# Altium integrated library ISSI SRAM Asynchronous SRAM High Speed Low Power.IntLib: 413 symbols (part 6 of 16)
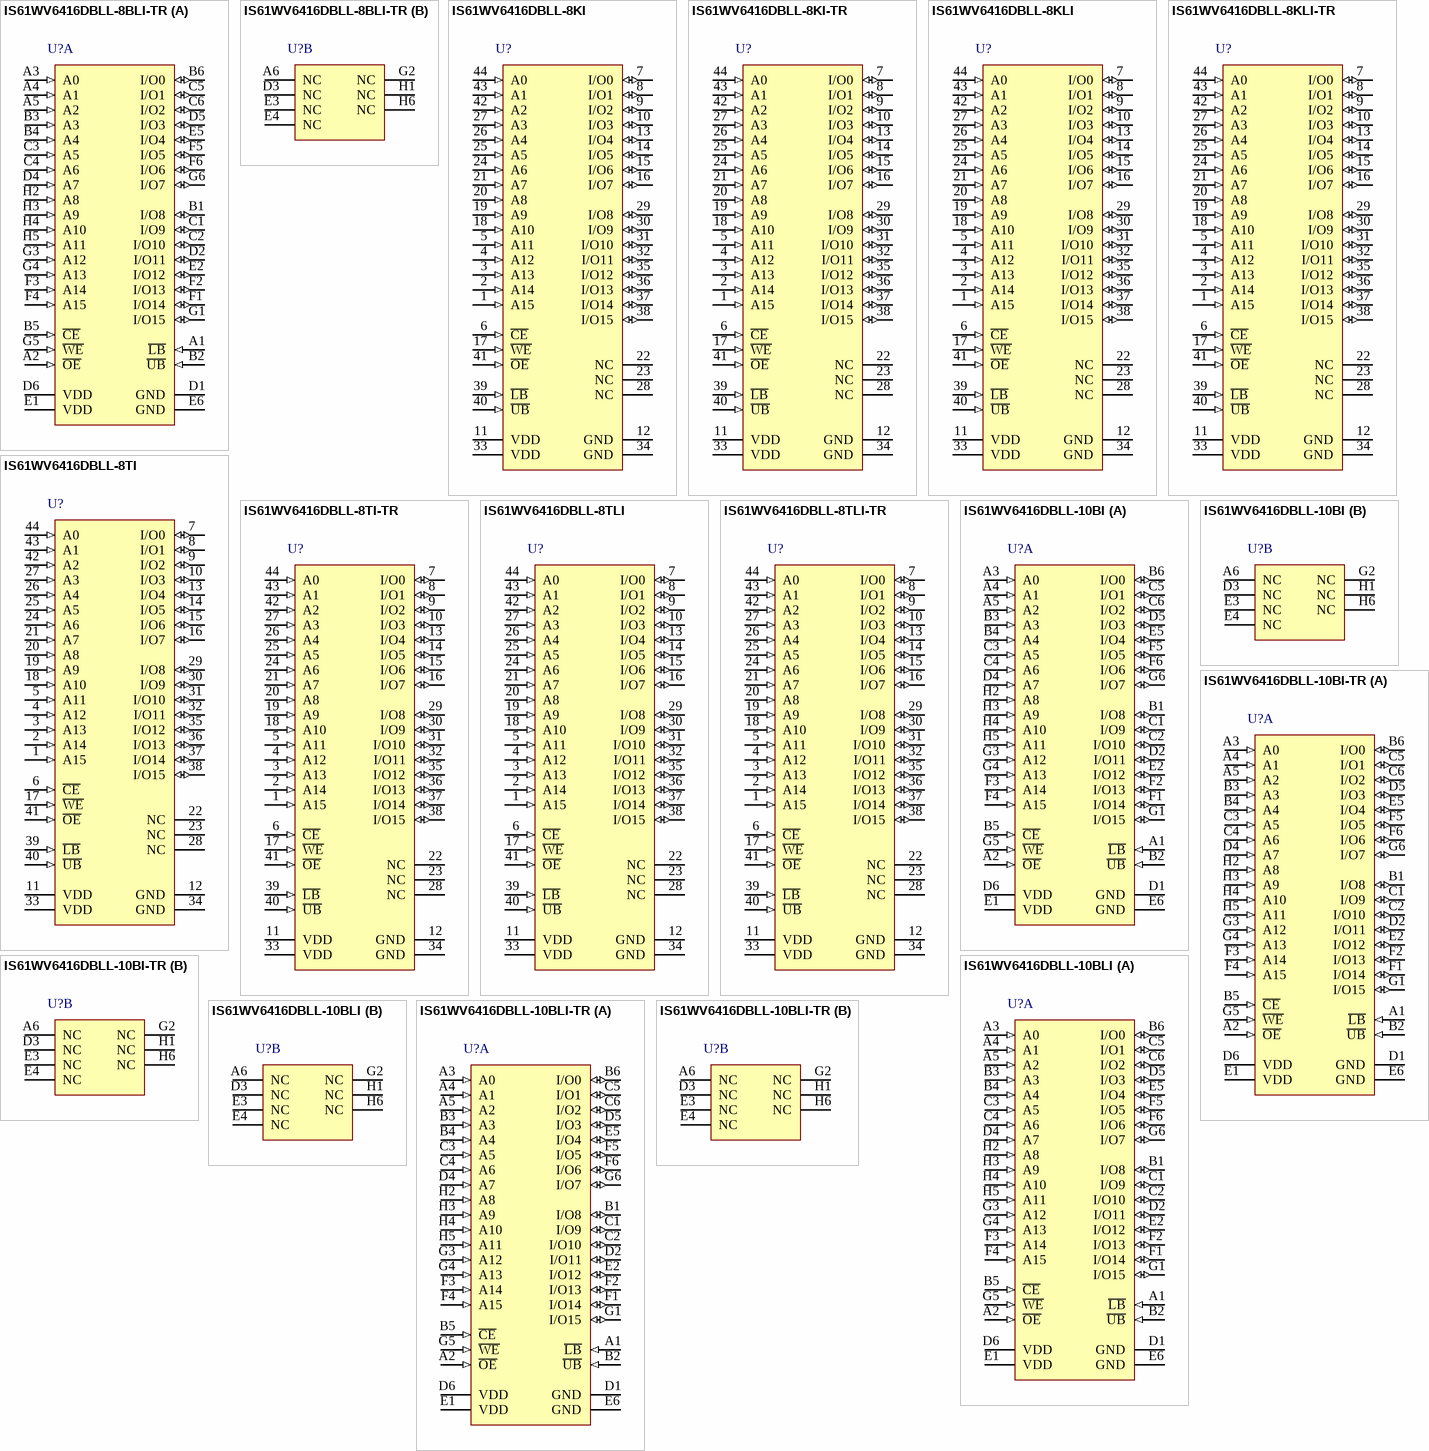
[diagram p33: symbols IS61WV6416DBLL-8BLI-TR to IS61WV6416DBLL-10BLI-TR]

## IS61WV6416DBLL-8BLI-TR
designator U?
1 M High Speed Asynchronous CMOS SRAM, 64 K x 16, -40 to 85 degC, 48-Pin BGA (TF-BGA-48), Pb-Free; Manufacturer: Integrated Silicon Solution Inc (ISSI); PartNumber: IS61WV6416DBLL-8BLI-TR; Density: 1M; Organization: 64K x 16; Packing: Tape & Reel; Speed (ns): 8
footprint ISSI-TF-BGA-48-6000X8000DE (BGA, 48-Balls, Body 8x6mm, Pitch 0.75mm)
part A pins: A1 ~{LB} (in) "Lower-byte Control (I/O0-I/O7)", A2 ~{OE} (in) "Output Enable Input", A3 A0 (in) "Address Input", A4 A1 (in) "Address Input", A5 A2 (in) "Address Input", B1 I/O8 (io) "Data Input/Output", B2 ~{UB} (in) "Upper-byte Control (I/O8-I/O15)", B3 A3 (in) "Address Input", B4 A4 (in) "Address Input", B5 ~{CE} (in) "Chip Enable Input", B6 I/O0 (io) "Data Input/Output", C1 I/O9 (io) "Data Input/Output", C2 I/O10 (io) "Data Input/Output", C3 A5 (in) "Address Input", C4 A6 (in) "Address Input", C5 I/O1 (io) "Data Input/Output", C6 I/O2 (io) "Data Input/Output", D1 GND (power) "Ground", D2 I/O11 (io) "Data Input/Output", D4 A7 (in) "Address Input", D5 I/O3 (io) "Data Input/Output", D6 VDD (power) "Power", E1 VDD (power) "Power", E2 I/O12 (io) "Data Input/Output", E5 I/O4 (io) "Data Input/Output", E6 GND (power) "Ground", F1 I/O14 (io) "Data Input/Output", F2 I/O13 (io) "Data Input/Output", F3 A14 (in) "Address Input", F4 A15 (in) "Address Input", F5 I/O5 (io) "Data Input/Output", F6 I/O6 (io) "Data Input/Output", G1 I/O15 (io) "Data Input/Output", G3 A12 (in) "Address Input", G4 A13 (in) "Address Input", G5 ~{WE} (in) "Write Enable Input", G6 I/O7 (io) "Data Input/Output", H2 A8 (in) "Address Input", H3 A9 (in) "Address Input", H4 A10 (in) "Address Input", H5 A11 (in) "Address Input"
part B pins: A6 NC "No Connection", D3 NC "No Connection", E3 NC "No Connection", E4 NC "No Connection", G2 NC "No Connection", H1 NC "No Connection", H6 NC "No Connection"

## IS61WV6416DBLL-8KI
designator U?
1 M High Speed Asynchronous CMOS SRAM, 64 K x 16, -40 to 85 degC, 44-Pin SOJ (SOJ-44); Manufacturer: Integrated Silicon Solution Inc (ISSI); PartNumber: IS61WV6416DBLL-8KI; Density: 1M; Organization: 64K x 16; Packing: Tray / Tube; Speed (ns): 8
footprint ISSI-SOJ-44_N (SOJ, 44-Leads, Body 28.7x10.29mm, Pitch 1.27mm, IPC Medium Density)
pins: 1 A15 (in) "Address Inputs", 2 A14 (in) "Address Inputs", 3 A13 (in) "Address Inputs", 4 A12 (in) "Address Inputs", 5 A11 (in) "Address Inputs", 6 ~{CE} (in) "Chip Enable Input", 7 I/O0 (io) "Data Inputs/Outputs", 8 I/O1 (io) "Data Inputs/Outputs", 9 I/O2 (io) "Data Inputs/Outputs", 10 I/O3 (io) "Data Inputs/Outputs", 11 VDD (power) "Power", 12 GND (power) "Ground", 13 I/O4 (io) "Data Inputs/Outputs", 14 I/O5 (io) "Data Inputs/Outputs", 15 I/O6 (io) "Data Inputs/Outputs", 16 I/O7 (io) "Data Inputs/Outputs", 17 ~{WE} (in) "Write Enable Input", 18 A10 (in) "Address Inputs", 19 A9 (in) "Address Inputs", 20 A8 (in) "Address Inputs", 21 A7 (in) "Address Inputs", 22 NC "No Connection", 23 NC "No Connection", 24 A6 (in) "Address Inputs", 25 A5 (in) "Address Inputs", 26 A4 (in) "Address Inputs", 27 A3 (in) "Address Inputs", 28 NC "No Connection", 29 I/O8 (io) "Data Inputs/Outputs", 30 I/O9 (io) "Data Inputs/Outputs", 31 I/O10 (io) "Data Inputs/Outputs", 32 I/O11 (io) "Data Inputs/Outputs", 33 VDD (power) "Power", 34 GND (power) "Ground", 35 I/O12 (io) "Data Inputs/Outputs", 36 I/O13 (io) "Data Inputs/Outputs", 37 I/O14 (io) "Data Inputs/Outputs", 38 I/O15 (io) "Data Inputs/Outputs", 39 ~{LB} (in) "Lower-byte Control (I/O0-I/O7)", 40 ~{UB} (in) "Upper-byte Control (I/O8-I/O15)", 41 ~{OE} (in) "Output Enable Input", 42 A2 (in) "Address Inputs", 43 A1 (in) "Address Inputs", 44 A0 (in) "Address Inputs"

## IS61WV6416DBLL-8KI-TR
designator U?
1 M High Speed Asynchronous CMOS SRAM, 64 K x 16, -40 to 85 degC, 44-Pin SOJ (SOJ-44); Manufacturer: Integrated Silicon Solution Inc (ISSI); PartNumber: IS61WV6416DBLL-8KI-TR; Density: 1M; Organization: 64K x 16; Packing: Tape & Reel; Speed (ns): 8
footprint ISSI-SOJ-44_N (SOJ, 44-Leads, Body 28.7x10.29mm, Pitch 1.27mm, IPC Medium Density)
pins: 1 A15 (in) "Address Inputs", 2 A14 (in) "Address Inputs", 3 A13 (in) "Address Inputs", 4 A12 (in) "Address Inputs", 5 A11 (in) "Address Inputs", 6 ~{CE} (in) "Chip Enable Input", 7 I/O0 (io) "Data Inputs/Outputs", 8 I/O1 (io) "Data Inputs/Outputs", 9 I/O2 (io) "Data Inputs/Outputs", 10 I/O3 (io) "Data Inputs/Outputs", 11 VDD (power) "Power", 12 GND (power) "Ground", 13 I/O4 (io) "Data Inputs/Outputs", 14 I/O5 (io) "Data Inputs/Outputs", 15 I/O6 (io) "Data Inputs/Outputs", 16 I/O7 (io) "Data Inputs/Outputs", 17 ~{WE} (in) "Write Enable Input", 18 A10 (in) "Address Inputs", 19 A9 (in) "Address Inputs", 20 A8 (in) "Address Inputs", 21 A7 (in) "Address Inputs", 22 NC "No Connection", 23 NC "No Connection", 24 A6 (in) "Address Inputs", 25 A5 (in) "Address Inputs", 26 A4 (in) "Address Inputs", 27 A3 (in) "Address Inputs", 28 NC "No Connection", 29 I/O8 (io) "Data Inputs/Outputs", 30 I/O9 (io) "Data Inputs/Outputs", 31 I/O10 (io) "Data Inputs/Outputs", 32 I/O11 (io) "Data Inputs/Outputs", 33 VDD (power) "Power", 34 GND (power) "Ground", 35 I/O12 (io) "Data Inputs/Outputs", 36 I/O13 (io) "Data Inputs/Outputs", 37 I/O14 (io) "Data Inputs/Outputs", 38 I/O15 (io) "Data Inputs/Outputs", 39 ~{LB} (in) "Lower-byte Control (I/O0-I/O7)", 40 ~{UB} (in) "Upper-byte Control (I/O8-I/O15)", 41 ~{OE} (in) "Output Enable Input", 42 A2 (in) "Address Inputs", 43 A1 (in) "Address Inputs", 44 A0 (in) "Address Inputs"

## IS61WV6416DBLL-8KLI
designator U?
1 M High Speed Asynchronous CMOS SRAM, 64 K x 16, -40 to 85 degC, 44-Pin SOJ (SOJ-44), Pb-Free; Manufacturer: Integrated Silicon Solution Inc (ISSI); PartNumber: IS61WV6416DBLL-8KLI; Density: 1M; Organization: 64K x 16; Packing: Tray / Tube; Speed (ns): 8
footprint ISSI-SOJ-44_N (SOJ, 44-Leads, Body 28.7x10.29mm, Pitch 1.27mm, IPC Medium Density)
pins: 1 A15 (in) "Address Inputs", 2 A14 (in) "Address Inputs", 3 A13 (in) "Address Inputs", 4 A12 (in) "Address Inputs", 5 A11 (in) "Address Inputs", 6 ~{CE} (in) "Chip Enable Input", 7 I/O0 (io) "Data Inputs/Outputs", 8 I/O1 (io) "Data Inputs/Outputs", 9 I/O2 (io) "Data Inputs/Outputs", 10 I/O3 (io) "Data Inputs/Outputs", 11 VDD (power) "Power", 12 GND (power) "Ground", 13 I/O4 (io) "Data Inputs/Outputs", 14 I/O5 (io) "Data Inputs/Outputs", 15 I/O6 (io) "Data Inputs/Outputs", 16 I/O7 (io) "Data Inputs/Outputs", 17 ~{WE} (in) "Write Enable Input", 18 A10 (in) "Address Inputs", 19 A9 (in) "Address Inputs", 20 A8 (in) "Address Inputs", 21 A7 (in) "Address Inputs", 22 NC "No Connection", 23 NC "No Connection", 24 A6 (in) "Address Inputs", 25 A5 (in) "Address Inputs", 26 A4 (in) "Address Inputs", 27 A3 (in) "Address Inputs", 28 NC "No Connection", 29 I/O8 (io) "Data Inputs/Outputs", 30 I/O9 (io) "Data Inputs/Outputs", 31 I/O10 (io) "Data Inputs/Outputs", 32 I/O11 (io) "Data Inputs/Outputs", 33 VDD (power) "Power", 34 GND (power) "Ground", 35 I/O12 (io) "Data Inputs/Outputs", 36 I/O13 (io) "Data Inputs/Outputs", 37 I/O14 (io) "Data Inputs/Outputs", 38 I/O15 (io) "Data Inputs/Outputs", 39 ~{LB} (in) "Lower-byte Control (I/O0-I/O7)", 40 ~{UB} (in) "Upper-byte Control (I/O8-I/O15)", 41 ~{OE} (in) "Output Enable Input", 42 A2 (in) "Address Inputs", 43 A1 (in) "Address Inputs", 44 A0 (in) "Address Inputs"

## IS61WV6416DBLL-8KLI-TR
designator U?
1 M High Speed Asynchronous CMOS SRAM, 64 K x 16, -40 to 85 degC, 44-Pin SOJ (SOJ-44), Pb-Free; Manufacturer: Integrated Silicon Solution Inc (ISSI); PartNumber: IS61WV6416DBLL-8KLI-TR; Density: 1M; Organization: 64K x 16; Packing: Tape & Reel; Speed (ns): 8
footprint ISSI-SOJ-44_N (SOJ, 44-Leads, Body 28.7x10.29mm, Pitch 1.27mm, IPC Medium Density)
pins: 1 A15 (in) "Address Inputs", 2 A14 (in) "Address Inputs", 3 A13 (in) "Address Inputs", 4 A12 (in) "Address Inputs", 5 A11 (in) "Address Inputs", 6 ~{CE} (in) "Chip Enable Input", 7 I/O0 (io) "Data Inputs/Outputs", 8 I/O1 (io) "Data Inputs/Outputs", 9 I/O2 (io) "Data Inputs/Outputs", 10 I/O3 (io) "Data Inputs/Outputs", 11 VDD (power) "Power", 12 GND (power) "Ground", 13 I/O4 (io) "Data Inputs/Outputs", 14 I/O5 (io) "Data Inputs/Outputs", 15 I/O6 (io) "Data Inputs/Outputs", 16 I/O7 (io) "Data Inputs/Outputs", 17 ~{WE} (in) "Write Enable Input", 18 A10 (in) "Address Inputs", 19 A9 (in) "Address Inputs", 20 A8 (in) "Address Inputs", 21 A7 (in) "Address Inputs", 22 NC "No Connection", 23 NC "No Connection", 24 A6 (in) "Address Inputs", 25 A5 (in) "Address Inputs", 26 A4 (in) "Address Inputs", 27 A3 (in) "Address Inputs", 28 NC "No Connection", 29 I/O8 (io) "Data Inputs/Outputs", 30 I/O9 (io) "Data Inputs/Outputs", 31 I/O10 (io) "Data Inputs/Outputs", 32 I/O11 (io) "Data Inputs/Outputs", 33 VDD (power) "Power", 34 GND (power) "Ground", 35 I/O12 (io) "Data Inputs/Outputs", 36 I/O13 (io) "Data Inputs/Outputs", 37 I/O14 (io) "Data Inputs/Outputs", 38 I/O15 (io) "Data Inputs/Outputs", 39 ~{LB} (in) "Lower-byte Control (I/O0-I/O7)", 40 ~{UB} (in) "Upper-byte Control (I/O8-I/O15)", 41 ~{OE} (in) "Output Enable Input", 42 A2 (in) "Address Inputs", 43 A1 (in) "Address Inputs", 44 A0 (in) "Address Inputs"

## IS61WV6416DBLL-8TI
designator U?
1 M High Speed Asynchronous CMOS SRAM, 64 K x 16, -40 to 85 degC, 44-Pin SOP (TSOP-2-44); Manufacturer: Integrated Silicon Solution Inc (ISSI); PartNumber: IS61WV6416DBLL-8TI; Density: 1M; Organization: 64K x 16; Packing: Tray / Tube; Speed (ns): 8
footprint ISSI-TSOP-2-44_N (SOP, 44-Leads, Body 18.5x10.3mm, Pitch 0.8mm, IPC Medium Density)
pins: 1 A15 (in) "Address Input", 2 A14 (in) "Address Input", 3 A13 (in) "Address Input", 4 A12 (in) "Address Input", 5 A11 (in) "Address Input", 6 ~{CE} (in) "Chip Enable Input", 7 I/O0 (io) "Data Input/Output", 8 I/O1 (io) "Data Input/Output", 9 I/O2 (io) "Data Input/Output", 10 I/O3 (io) "Data Input/Output", 11 VDD (power) "Power", 12 GND (power) "Ground", 13 I/O4 (io) "Data Input/Output", 14 I/O5 (io) "Data Input/Output", 15 I/O6 (io) "Data Input/Output", 16 I/O7 (io) "Data Input/Output", 17 ~{WE} (in) "Write Enable Input", 18 A10 (in) "Address Input", 19 A9 (in) "Address Input", 20 A8 (in) "Address Input", 21 A7 (in) "Address Input", 22 NC "No Connection", 23 NC "No Connection", 24 A6 (in) "Address Input", 25 A5 (in) "Address Input", 26 A4 (in) "Address Input", 27 A3 (in) "Address Input", 28 NC "No Connection", 29 I/O8 (io) "Data Input/Output", 30 I/O9 (io) "Data Input/Output", 31 I/O10 (io) "Data Input/Output", 32 I/O11 (io) "Data Input/Output", 33 VDD (power) "Power", 34 GND (power) "Ground", 35 I/O12 (io) "Data Input/Output", 36 I/O13 (io) "Data Input/Output", 37 I/O14 (io) "Data Input/Output", 38 I/O15 (io) "Data Input/Output", 39 ~{LB} (in) "Lower-byte Control (I/O0-I/O7)", 40 ~{UB} (in) "Upper-byte Control (I/O8-I/O15)", 41 ~{OE} (in) "Output Enable Input", 42 A2 (in) "Address Input", 43 A1 (in) "Address Input", 44 A0 (in) "Address Input"

## IS61WV6416DBLL-8TI-TR
designator U?
1 M High Speed Asynchronous CMOS SRAM, 64 K x 16, -40 to 85 degC, 44-Pin SOP (TSOP-2-44); Manufacturer: Integrated Silicon Solution Inc (ISSI); PartNumber: IS61WV6416DBLL-8TI-TR; Density: 1M; Organization: 64K x 16; Packing: Tape & Reel; Speed (ns): 8
footprint ISSI-TSOP-2-44_N (SOP, 44-Leads, Body 18.5x10.3mm, Pitch 0.8mm, IPC Medium Density)
pins: 1 A15 (in) "Address Input", 2 A14 (in) "Address Input", 3 A13 (in) "Address Input", 4 A12 (in) "Address Input", 5 A11 (in) "Address Input", 6 ~{CE} (in) "Chip Enable Input", 7 I/O0 (io) "Data Input/Output", 8 I/O1 (io) "Data Input/Output", 9 I/O2 (io) "Data Input/Output", 10 I/O3 (io) "Data Input/Output", 11 VDD (power) "Power", 12 GND (power) "Ground", 13 I/O4 (io) "Data Input/Output", 14 I/O5 (io) "Data Input/Output", 15 I/O6 (io) "Data Input/Output", 16 I/O7 (io) "Data Input/Output", 17 ~{WE} (in) "Write Enable Input", 18 A10 (in) "Address Input", 19 A9 (in) "Address Input", 20 A8 (in) "Address Input", 21 A7 (in) "Address Input", 22 NC "No Connection", 23 NC "No Connection", 24 A6 (in) "Address Input", 25 A5 (in) "Address Input", 26 A4 (in) "Address Input", 27 A3 (in) "Address Input", 28 NC "No Connection", 29 I/O8 (io) "Data Input/Output", 30 I/O9 (io) "Data Input/Output", 31 I/O10 (io) "Data Input/Output", 32 I/O11 (io) "Data Input/Output", 33 VDD (power) "Power", 34 GND (power) "Ground", 35 I/O12 (io) "Data Input/Output", 36 I/O13 (io) "Data Input/Output", 37 I/O14 (io) "Data Input/Output", 38 I/O15 (io) "Data Input/Output", 39 ~{LB} (in) "Lower-byte Control (I/O0-I/O7)", 40 ~{UB} (in) "Upper-byte Control (I/O8-I/O15)", 41 ~{OE} (in) "Output Enable Input", 42 A2 (in) "Address Input", 43 A1 (in) "Address Input", 44 A0 (in) "Address Input"

## IS61WV6416DBLL-8TLI
designator U?
1 M High Speed Asynchronous CMOS SRAM, 64 K x 16, -40 to 85 degC, 44-Pin SOP (TSOP-2-44), Pb-Free; Manufacturer: Integrated Silicon Solution Inc (ISSI); PartNumber: IS61WV6416DBLL-8TLI; Density: 1M; Organization: 64K x 16; Packing: Tray / Tube; Speed (ns): 8
footprint ISSI-TSOP-2-44_N (SOP, 44-Leads, Body 18.5x10.3mm, Pitch 0.8mm, IPC Medium Density)
pins: 1 A15 (in) "Address Input", 2 A14 (in) "Address Input", 3 A13 (in) "Address Input", 4 A12 (in) "Address Input", 5 A11 (in) "Address Input", 6 ~{CE} (in) "Chip Enable Input", 7 I/O0 (io) "Data Input/Output", 8 I/O1 (io) "Data Input/Output", 9 I/O2 (io) "Data Input/Output", 10 I/O3 (io) "Data Input/Output", 11 VDD (power) "Power", 12 GND (power) "Ground", 13 I/O4 (io) "Data Input/Output", 14 I/O5 (io) "Data Input/Output", 15 I/O6 (io) "Data Input/Output", 16 I/O7 (io) "Data Input/Output", 17 ~{WE} (in) "Write Enable Input", 18 A10 (in) "Address Input", 19 A9 (in) "Address Input", 20 A8 (in) "Address Input", 21 A7 (in) "Address Input", 22 NC "No Connection", 23 NC "No Connection", 24 A6 (in) "Address Input", 25 A5 (in) "Address Input", 26 A4 (in) "Address Input", 27 A3 (in) "Address Input", 28 NC "No Connection", 29 I/O8 (io) "Data Input/Output", 30 I/O9 (io) "Data Input/Output", 31 I/O10 (io) "Data Input/Output", 32 I/O11 (io) "Data Input/Output", 33 VDD (power) "Power", 34 GND (power) "Ground", 35 I/O12 (io) "Data Input/Output", 36 I/O13 (io) "Data Input/Output", 37 I/O14 (io) "Data Input/Output", 38 I/O15 (io) "Data Input/Output", 39 ~{LB} (in) "Lower-byte Control (I/O0-I/O7)", 40 ~{UB} (in) "Upper-byte Control (I/O8-I/O15)", 41 ~{OE} (in) "Output Enable Input", 42 A2 (in) "Address Input", 43 A1 (in) "Address Input", 44 A0 (in) "Address Input"

## IS61WV6416DBLL-8TLI-TR
designator U?
1 M High Speed Asynchronous CMOS SRAM, 64 K x 16, -40 to 85 degC, 44-Pin SOP (TSOP-2-44), Pb-Free; Manufacturer: Integrated Silicon Solution Inc (ISSI); PartNumber: IS61WV6416DBLL-8TLI-TR; Density: 1M; Organization: 64K x 16; Packing: Tape & Reel; Speed (ns): 8
footprint ISSI-TSOP-2-44_N (SOP, 44-Leads, Body 18.5x10.3mm, Pitch 0.8mm, IPC Medium Density)
pins: 1 A15 (in) "Address Input", 2 A14 (in) "Address Input", 3 A13 (in) "Address Input", 4 A12 (in) "Address Input", 5 A11 (in) "Address Input", 6 ~{CE} (in) "Chip Enable Input", 7 I/O0 (io) "Data Input/Output", 8 I/O1 (io) "Data Input/Output", 9 I/O2 (io) "Data Input/Output", 10 I/O3 (io) "Data Input/Output", 11 VDD (power) "Power", 12 GND (power) "Ground", 13 I/O4 (io) "Data Input/Output", 14 I/O5 (io) "Data Input/Output", 15 I/O6 (io) "Data Input/Output", 16 I/O7 (io) "Data Input/Output", 17 ~{WE} (in) "Write Enable Input", 18 A10 (in) "Address Input", 19 A9 (in) "Address Input", 20 A8 (in) "Address Input", 21 A7 (in) "Address Input", 22 NC "No Connection", 23 NC "No Connection", 24 A6 (in) "Address Input", 25 A5 (in) "Address Input", 26 A4 (in) "Address Input", 27 A3 (in) "Address Input", 28 NC "No Connection", 29 I/O8 (io) "Data Input/Output", 30 I/O9 (io) "Data Input/Output", 31 I/O10 (io) "Data Input/Output", 32 I/O11 (io) "Data Input/Output", 33 VDD (power) "Power", 34 GND (power) "Ground", 35 I/O12 (io) "Data Input/Output", 36 I/O13 (io) "Data Input/Output", 37 I/O14 (io) "Data Input/Output", 38 I/O15 (io) "Data Input/Output", 39 ~{LB} (in) "Lower-byte Control (I/O0-I/O7)", 40 ~{UB} (in) "Upper-byte Control (I/O8-I/O15)", 41 ~{OE} (in) "Output Enable Input", 42 A2 (in) "Address Input", 43 A1 (in) "Address Input", 44 A0 (in) "Address Input"

## IS61WV6416DBLL-10BI
designator U?
1 M High Speed Asynchronous CMOS SRAM, 64 K x 16, -40 to 85 degC, 48-Pin BGA (TF-BGA-48); Manufacturer: Integrated Silicon Solution Inc (ISSI); PartNumber: IS61WV6416DBLL-10BI; Density: 1M; Organization: 64K x 16; Packing: Tray / Tube; Speed (ns): 10
footprint ISSI-TF-BGA-48-6000X8000DE (BGA, 48-Balls, Body 8x6mm, Pitch 0.75mm)
part A pins: A1 ~{LB} (in) "Lower-byte Control (I/O0-I/O7)", A2 ~{OE} (in) "Output Enable Input", A3 A0 (in) "Address Input", A4 A1 (in) "Address Input", A5 A2 (in) "Address Input", B1 I/O8 (io) "Data Input/Output", B2 ~{UB} (in) "Upper-byte Control (I/O8-I/O15)", B3 A3 (in) "Address Input", B4 A4 (in) "Address Input", B5 ~{CE} (in) "Chip Enable Input", B6 I/O0 (io) "Data Input/Output", C1 I/O9 (io) "Data Input/Output", C2 I/O10 (io) "Data Input/Output", C3 A5 (in) "Address Input", C4 A6 (in) "Address Input", C5 I/O1 (io) "Data Input/Output", C6 I/O2 (io) "Data Input/Output", D1 GND (power) "Ground", D2 I/O11 (io) "Data Input/Output", D4 A7 (in) "Address Input", D5 I/O3 (io) "Data Input/Output", D6 VDD (power) "Power", E1 VDD (power) "Power", E2 I/O12 (io) "Data Input/Output", E5 I/O4 (io) "Data Input/Output", E6 GND (power) "Ground", F1 I/O14 (io) "Data Input/Output", F2 I/O13 (io) "Data Input/Output", F3 A14 (in) "Address Input", F4 A15 (in) "Address Input", F5 I/O5 (io) "Data Input/Output", F6 I/O6 (io) "Data Input/Output", G1 I/O15 (io) "Data Input/Output", G3 A12 (in) "Address Input", G4 A13 (in) "Address Input", G5 ~{WE} (in) "Write Enable Input", G6 I/O7 (io) "Data Input/Output", H2 A8 (in) "Address Input", H3 A9 (in) "Address Input", H4 A10 (in) "Address Input", H5 A11 (in) "Address Input"
part B pins: A6 NC "No Connection", D3 NC "No Connection", E3 NC "No Connection", E4 NC "No Connection", G2 NC "No Connection", H1 NC "No Connection", H6 NC "No Connection"

## IS61WV6416DBLL-10BI-TR
designator U?
1 M High Speed Asynchronous CMOS SRAM, 64 K x 16, -40 to 85 degC, 48-Pin BGA (TF-BGA-48); Manufacturer: Integrated Silicon Solution Inc (ISSI); PartNumber: IS61WV6416DBLL-10BI-TR; Density: 1M; Organization: 64K x 16; Packing: Tape & Reel; Speed (ns): 10
footprint ISSI-TF-BGA-48-6000X8000DE (BGA, 48-Balls, Body 8x6mm, Pitch 0.75mm)
part A pins: A1 ~{LB} (in) "Lower-byte Control (I/O0-I/O7)", A2 ~{OE} (in) "Output Enable Input", A3 A0 (in) "Address Input", A4 A1 (in) "Address Input", A5 A2 (in) "Address Input", B1 I/O8 (io) "Data Input/Output", B2 ~{UB} (in) "Upper-byte Control (I/O8-I/O15)", B3 A3 (in) "Address Input", B4 A4 (in) "Address Input", B5 ~{CE} (in) "Chip Enable Input", B6 I/O0 (io) "Data Input/Output", C1 I/O9 (io) "Data Input/Output", C2 I/O10 (io) "Data Input/Output", C3 A5 (in) "Address Input", C4 A6 (in) "Address Input", C5 I/O1 (io) "Data Input/Output", C6 I/O2 (io) "Data Input/Output", D1 GND (power) "Ground", D2 I/O11 (io) "Data Input/Output", D4 A7 (in) "Address Input", D5 I/O3 (io) "Data Input/Output", D6 VDD (power) "Power", E1 VDD (power) "Power", E2 I/O12 (io) "Data Input/Output", E5 I/O4 (io) "Data Input/Output", E6 GND (power) "Ground", F1 I/O14 (io) "Data Input/Output", F2 I/O13 (io) "Data Input/Output", F3 A14 (in) "Address Input", F4 A15 (in) "Address Input", F5 I/O5 (io) "Data Input/Output", F6 I/O6 (io) "Data Input/Output", G1 I/O15 (io) "Data Input/Output", G3 A12 (in) "Address Input", G4 A13 (in) "Address Input", G5 ~{WE} (in) "Write Enable Input", G6 I/O7 (io) "Data Input/Output", H2 A8 (in) "Address Input", H3 A9 (in) "Address Input", H4 A10 (in) "Address Input", H5 A11 (in) "Address Input"
part B pins: A6 NC "No Connection", D3 NC "No Connection", E3 NC "No Connection", E4 NC "No Connection", G2 NC "No Connection", H1 NC "No Connection", H6 NC "No Connection"

## IS61WV6416DBLL-10BLI
designator U?
1 M High Speed Asynchronous CMOS SRAM, 64 K x 16, -40 to 85 degC, 48-Pin BGA (TF-BGA-48), Pb-Free; Manufacturer: Integrated Silicon Solution Inc (ISSI); PartNumber: IS61WV6416DBLL-10BLI; Density: 1M; Organization: 64K x 16; Packing: Tray / Tube; Speed (ns): 10
footprint ISSI-TF-BGA-48-6000X8000DE (BGA, 48-Balls, Body 8x6mm, Pitch 0.75mm)
part A pins: A1 ~{LB} (in) "Lower-byte Control (I/O0-I/O7)", A2 ~{OE} (in) "Output Enable Input", A3 A0 (in) "Address Input", A4 A1 (in) "Address Input", A5 A2 (in) "Address Input", B1 I/O8 (io) "Data Input/Output", B2 ~{UB} (in) "Upper-byte Control (I/O8-I/O15)", B3 A3 (in) "Address Input", B4 A4 (in) "Address Input", B5 ~{CE} (in) "Chip Enable Input", B6 I/O0 (io) "Data Input/Output", C1 I/O9 (io) "Data Input/Output", C2 I/O10 (io) "Data Input/Output", C3 A5 (in) "Address Input", C4 A6 (in) "Address Input", C5 I/O1 (io) "Data Input/Output", C6 I/O2 (io) "Data Input/Output", D1 GND (power) "Ground", D2 I/O11 (io) "Data Input/Output", D4 A7 (in) "Address Input", D5 I/O3 (io) "Data Input/Output", D6 VDD (power) "Power", E1 VDD (power) "Power", E2 I/O12 (io) "Data Input/Output", E5 I/O4 (io) "Data Input/Output", E6 GND (power) "Ground", F1 I/O14 (io) "Data Input/Output", F2 I/O13 (io) "Data Input/Output", F3 A14 (in) "Address Input", F4 A15 (in) "Address Input", F5 I/O5 (io) "Data Input/Output", F6 I/O6 (io) "Data Input/Output", G1 I/O15 (io) "Data Input/Output", G3 A12 (in) "Address Input", G4 A13 (in) "Address Input", G5 ~{WE} (in) "Write Enable Input", G6 I/O7 (io) "Data Input/Output", H2 A8 (in) "Address Input", H3 A9 (in) "Address Input", H4 A10 (in) "Address Input", H5 A11 (in) "Address Input"
part B pins: A6 NC "No Connection", D3 NC "No Connection", E3 NC "No Connection", E4 NC "No Connection", G2 NC "No Connection", H1 NC "No Connection", H6 NC "No Connection"

## IS61WV6416DBLL-10BLI-TR
designator U?
1 M High Speed Asynchronous CMOS SRAM, 64 K x 16, -40 to 85 degC, 48-Pin BGA (TF-BGA-48), Pb-Free; Manufacturer: Integrated Silicon Solution Inc (ISSI); PartNumber: IS61WV6416DBLL-10BLI-TR; Density: 1M; Organization: 64K x 16; Packing: Tape & Reel; Speed (ns): 10
footprint ISSI-TF-BGA-48-6000X8000DE (BGA, 48-Balls, Body 8x6mm, Pitch 0.75mm)
part A pins: A1 ~{LB} (in) "Lower-byte Control (I/O0-I/O7)", A2 ~{OE} (in) "Output Enable Input", A3 A0 (in) "Address Input", A4 A1 (in) "Address Input", A5 A2 (in) "Address Input", B1 I/O8 (io) "Data Input/Output", B2 ~{UB} (in) "Upper-byte Control (I/O8-I/O15)", B3 A3 (in) "Address Input", B4 A4 (in) "Address Input", B5 ~{CE} (in) "Chip Enable Input", B6 I/O0 (io) "Data Input/Output", C1 I/O9 (io) "Data Input/Output", C2 I/O10 (io) "Data Input/Output", C3 A5 (in) "Address Input", C4 A6 (in) "Address Input", C5 I/O1 (io) "Data Input/Output", C6 I/O2 (io) "Data Input/Output", D1 GND (power) "Ground", D2 I/O11 (io) "Data Input/Output", D4 A7 (in) "Address Input", D5 I/O3 (io) "Data Input/Output", D6 VDD (power) "Power", E1 VDD (power) "Power", E2 I/O12 (io) "Data Input/Output", E5 I/O4 (io) "Data Input/Output", E6 GND (power) "Ground", F1 I/O14 (io) "Data Input/Output", F2 I/O13 (io) "Data Input/Output", F3 A14 (in) "Address Input", F4 A15 (in) "Address Input", F5 I/O5 (io) "Data Input/Output", F6 I/O6 (io) "Data Input/Output", G1 I/O15 (io) "Data Input/Output", G3 A12 (in) "Address Input", G4 A13 (in) "Address Input", G5 ~{WE} (in) "Write Enable Input", G6 I/O7 (io) "Data Input/Output", H2 A8 (in) "Address Input", H3 A9 (in) "Address Input", H4 A10 (in) "Address Input", H5 A11 (in) "Address Input"
part B pins: A6 NC "No Connection", D3 NC "No Connection", E3 NC "No Connection", E4 NC "No Connection", G2 NC "No Connection", H1 NC "No Connection", H6 NC "No Connection"

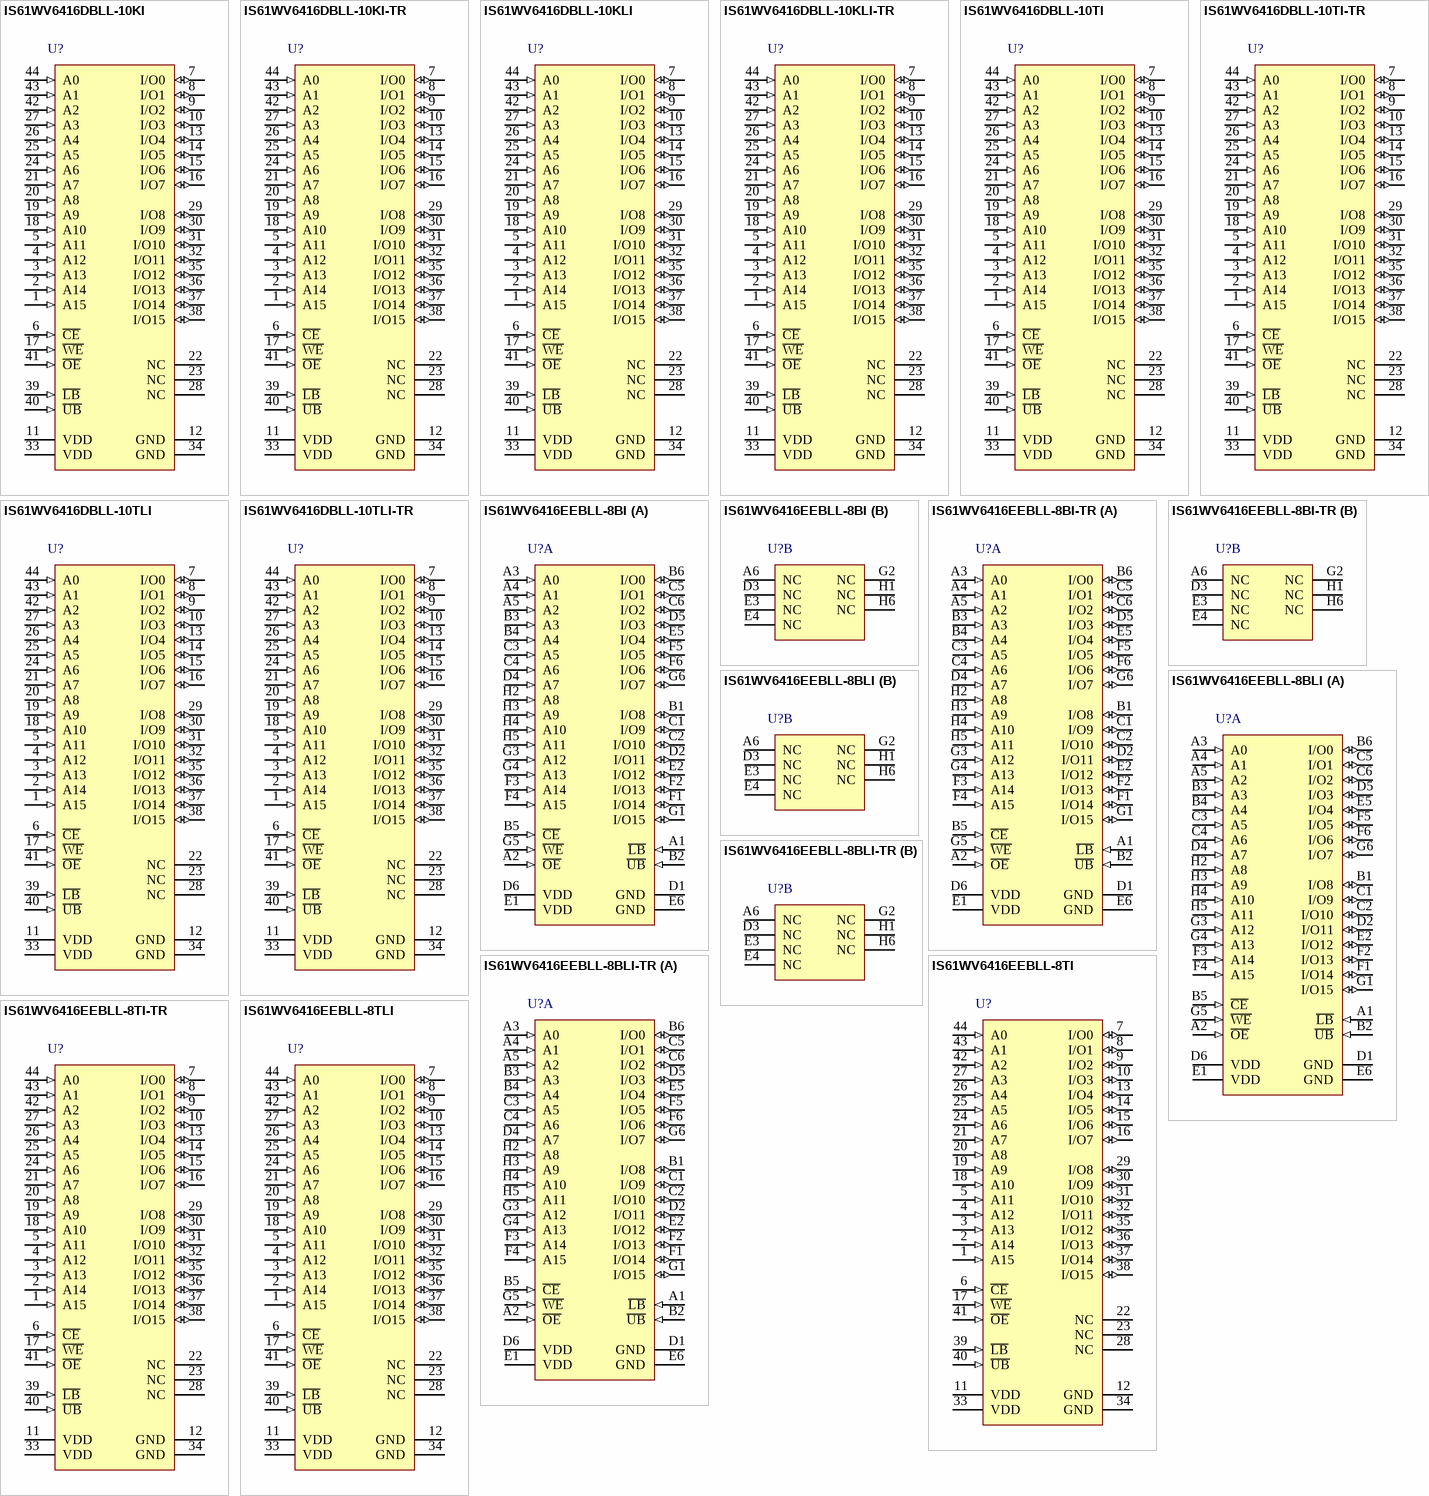
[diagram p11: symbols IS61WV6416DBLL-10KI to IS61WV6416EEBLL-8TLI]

## IS61WV6416DBLL-10KI
designator U?
1 M High Speed Asynchronous CMOS SRAM, 64 K x 16, -40 to 85 degC, 44-Pin SOJ (SOJ-44); Manufacturer: Integrated Silicon Solution Inc (ISSI); PartNumber: IS61WV6416DBLL-10KI; Density: 1M; Organization: 64K x 16; Packing: Tray / Tube; Speed (ns): 10
footprint ISSI-SOJ-44_N (SOJ, 44-Leads, Body 28.7x10.29mm, Pitch 1.27mm, IPC Medium Density)
pins: 1 A15 (in) "Address Inputs", 2 A14 (in) "Address Inputs", 3 A13 (in) "Address Inputs", 4 A12 (in) "Address Inputs", 5 A11 (in) "Address Inputs", 6 ~{CE} (in) "Chip Enable Input", 7 I/O0 (io) "Data Inputs/Outputs", 8 I/O1 (io) "Data Inputs/Outputs", 9 I/O2 (io) "Data Inputs/Outputs", 10 I/O3 (io) "Data Inputs/Outputs", 11 VDD (power) "Power", 12 GND (power) "Ground", 13 I/O4 (io) "Data Inputs/Outputs", 14 I/O5 (io) "Data Inputs/Outputs", 15 I/O6 (io) "Data Inputs/Outputs", 16 I/O7 (io) "Data Inputs/Outputs", 17 ~{WE} (in) "Write Enable Input", 18 A10 (in) "Address Inputs", 19 A9 (in) "Address Inputs", 20 A8 (in) "Address Inputs", 21 A7 (in) "Address Inputs", 22 NC "No Connection", 23 NC "No Connection", 24 A6 (in) "Address Inputs", 25 A5 (in) "Address Inputs", 26 A4 (in) "Address Inputs", 27 A3 (in) "Address Inputs", 28 NC "No Connection", 29 I/O8 (io) "Data Inputs/Outputs", 30 I/O9 (io) "Data Inputs/Outputs", 31 I/O10 (io) "Data Inputs/Outputs", 32 I/O11 (io) "Data Inputs/Outputs", 33 VDD (power) "Power", 34 GND (power) "Ground", 35 I/O12 (io) "Data Inputs/Outputs", 36 I/O13 (io) "Data Inputs/Outputs", 37 I/O14 (io) "Data Inputs/Outputs", 38 I/O15 (io) "Data Inputs/Outputs", 39 ~{LB} (in) "Lower-byte Control (I/O0-I/O7)", 40 ~{UB} (in) "Upper-byte Control (I/O8-I/O15)", 41 ~{OE} (in) "Output Enable Input", 42 A2 (in) "Address Inputs", 43 A1 (in) "Address Inputs", 44 A0 (in) "Address Inputs"

## IS61WV6416DBLL-10KI-TR
designator U?
1 M High Speed Asynchronous CMOS SRAM, 64 K x 16, -40 to 85 degC, 44-Pin SOJ (SOJ-44); Manufacturer: Integrated Silicon Solution Inc (ISSI); PartNumber: IS61WV6416DBLL-10KI-TR; Density: 1M; Organization: 64K x 16; Packing: Tape & Reel; Speed (ns): 10
footprint ISSI-SOJ-44_N (SOJ, 44-Leads, Body 28.7x10.29mm, Pitch 1.27mm, IPC Medium Density)
pins: 1 A15 (in) "Address Inputs", 2 A14 (in) "Address Inputs", 3 A13 (in) "Address Inputs", 4 A12 (in) "Address Inputs", 5 A11 (in) "Address Inputs", 6 ~{CE} (in) "Chip Enable Input", 7 I/O0 (io) "Data Inputs/Outputs", 8 I/O1 (io) "Data Inputs/Outputs", 9 I/O2 (io) "Data Inputs/Outputs", 10 I/O3 (io) "Data Inputs/Outputs", 11 VDD (power) "Power", 12 GND (power) "Ground", 13 I/O4 (io) "Data Inputs/Outputs", 14 I/O5 (io) "Data Inputs/Outputs", 15 I/O6 (io) "Data Inputs/Outputs", 16 I/O7 (io) "Data Inputs/Outputs", 17 ~{WE} (in) "Write Enable Input", 18 A10 (in) "Address Inputs", 19 A9 (in) "Address Inputs", 20 A8 (in) "Address Inputs", 21 A7 (in) "Address Inputs", 22 NC "No Connection", 23 NC "No Connection", 24 A6 (in) "Address Inputs", 25 A5 (in) "Address Inputs", 26 A4 (in) "Address Inputs", 27 A3 (in) "Address Inputs", 28 NC "No Connection", 29 I/O8 (io) "Data Inputs/Outputs", 30 I/O9 (io) "Data Inputs/Outputs", 31 I/O10 (io) "Data Inputs/Outputs", 32 I/O11 (io) "Data Inputs/Outputs", 33 VDD (power) "Power", 34 GND (power) "Ground", 35 I/O12 (io) "Data Inputs/Outputs", 36 I/O13 (io) "Data Inputs/Outputs", 37 I/O14 (io) "Data Inputs/Outputs", 38 I/O15 (io) "Data Inputs/Outputs", 39 ~{LB} (in) "Lower-byte Control (I/O0-I/O7)", 40 ~{UB} (in) "Upper-byte Control (I/O8-I/O15)", 41 ~{OE} (in) "Output Enable Input", 42 A2 (in) "Address Inputs", 43 A1 (in) "Address Inputs", 44 A0 (in) "Address Inputs"

## IS61WV6416DBLL-10KLI
designator U?
1 M High Speed Asynchronous CMOS SRAM, 64 K x 16, -40 to 85 degC, 44-Pin SOJ (SOJ-44), Pb-Free; Manufacturer: Integrated Silicon Solution Inc (ISSI); PartNumber: IS61WV6416DBLL-10KLI; Density: 1M; Organization: 64K x 16; Packing: Tray / Tube; Speed (ns): 10
footprint ISSI-SOJ-44_N (SOJ, 44-Leads, Body 28.7x10.29mm, Pitch 1.27mm, IPC Medium Density)
pins: 1 A15 (in) "Address Inputs", 2 A14 (in) "Address Inputs", 3 A13 (in) "Address Inputs", 4 A12 (in) "Address Inputs", 5 A11 (in) "Address Inputs", 6 ~{CE} (in) "Chip Enable Input", 7 I/O0 (io) "Data Inputs/Outputs", 8 I/O1 (io) "Data Inputs/Outputs", 9 I/O2 (io) "Data Inputs/Outputs", 10 I/O3 (io) "Data Inputs/Outputs", 11 VDD (power) "Power", 12 GND (power) "Ground", 13 I/O4 (io) "Data Inputs/Outputs", 14 I/O5 (io) "Data Inputs/Outputs", 15 I/O6 (io) "Data Inputs/Outputs", 16 I/O7 (io) "Data Inputs/Outputs", 17 ~{WE} (in) "Write Enable Input", 18 A10 (in) "Address Inputs", 19 A9 (in) "Address Inputs", 20 A8 (in) "Address Inputs", 21 A7 (in) "Address Inputs", 22 NC "No Connection", 23 NC "No Connection", 24 A6 (in) "Address Inputs", 25 A5 (in) "Address Inputs", 26 A4 (in) "Address Inputs", 27 A3 (in) "Address Inputs", 28 NC "No Connection", 29 I/O8 (io) "Data Inputs/Outputs", 30 I/O9 (io) "Data Inputs/Outputs", 31 I/O10 (io) "Data Inputs/Outputs", 32 I/O11 (io) "Data Inputs/Outputs", 33 VDD (power) "Power", 34 GND (power) "Ground", 35 I/O12 (io) "Data Inputs/Outputs", 36 I/O13 (io) "Data Inputs/Outputs", 37 I/O14 (io) "Data Inputs/Outputs", 38 I/O15 (io) "Data Inputs/Outputs", 39 ~{LB} (in) "Lower-byte Control (I/O0-I/O7)", 40 ~{UB} (in) "Upper-byte Control (I/O8-I/O15)", 41 ~{OE} (in) "Output Enable Input", 42 A2 (in) "Address Inputs", 43 A1 (in) "Address Inputs", 44 A0 (in) "Address Inputs"

## IS61WV6416DBLL-10KLI-TR
designator U?
1 M High Speed Asynchronous CMOS SRAM, 64 K x 16, -40 to 85 degC, 44-Pin SOJ (SOJ-44), Pb-Free; Manufacturer: Integrated Silicon Solution Inc (ISSI); PartNumber: IS61WV6416DBLL-10KLI-TR; Density: 1M; Organization: 64K x 16; Packing: Tape & Reel; Speed (ns): 10
footprint ISSI-SOJ-44_N (SOJ, 44-Leads, Body 28.7x10.29mm, Pitch 1.27mm, IPC Medium Density)
pins: 1 A15 (in) "Address Inputs", 2 A14 (in) "Address Inputs", 3 A13 (in) "Address Inputs", 4 A12 (in) "Address Inputs", 5 A11 (in) "Address Inputs", 6 ~{CE} (in) "Chip Enable Input", 7 I/O0 (io) "Data Inputs/Outputs", 8 I/O1 (io) "Data Inputs/Outputs", 9 I/O2 (io) "Data Inputs/Outputs", 10 I/O3 (io) "Data Inputs/Outputs", 11 VDD (power) "Power", 12 GND (power) "Ground", 13 I/O4 (io) "Data Inputs/Outputs", 14 I/O5 (io) "Data Inputs/Outputs", 15 I/O6 (io) "Data Inputs/Outputs", 16 I/O7 (io) "Data Inputs/Outputs", 17 ~{WE} (in) "Write Enable Input", 18 A10 (in) "Address Inputs", 19 A9 (in) "Address Inputs", 20 A8 (in) "Address Inputs", 21 A7 (in) "Address Inputs", 22 NC "No Connection", 23 NC "No Connection", 24 A6 (in) "Address Inputs", 25 A5 (in) "Address Inputs", 26 A4 (in) "Address Inputs", 27 A3 (in) "Address Inputs", 28 NC "No Connection", 29 I/O8 (io) "Data Inputs/Outputs", 30 I/O9 (io) "Data Inputs/Outputs", 31 I/O10 (io) "Data Inputs/Outputs", 32 I/O11 (io) "Data Inputs/Outputs", 33 VDD (power) "Power", 34 GND (power) "Ground", 35 I/O12 (io) "Data Inputs/Outputs", 36 I/O13 (io) "Data Inputs/Outputs", 37 I/O14 (io) "Data Inputs/Outputs", 38 I/O15 (io) "Data Inputs/Outputs", 39 ~{LB} (in) "Lower-byte Control (I/O0-I/O7)", 40 ~{UB} (in) "Upper-byte Control (I/O8-I/O15)", 41 ~{OE} (in) "Output Enable Input", 42 A2 (in) "Address Inputs", 43 A1 (in) "Address Inputs", 44 A0 (in) "Address Inputs"

## IS61WV6416DBLL-10TI
designator U?
1 M High Speed Asynchronous CMOS SRAM, 64 K x 16, -40 to 85 degC, 44-Pin SOP (TSOP-2-44); Manufacturer: Integrated Silicon Solution Inc (ISSI); PartNumber: IS61WV6416DBLL-10TI; Density: 1M; Organization: 64K x 16; Packing: Tray / Tube; Speed (ns): 10
footprint ISSI-TSOP-2-44_N (SOP, 44-Leads, Body 18.5x10.3mm, Pitch 0.8mm, IPC Medium Density)
pins: 1 A15 (in) "Address Input", 2 A14 (in) "Address Input", 3 A13 (in) "Address Input", 4 A12 (in) "Address Input", 5 A11 (in) "Address Input", 6 ~{CE} (in) "Chip Enable Input", 7 I/O0 (io) "Data Input/Output", 8 I/O1 (io) "Data Input/Output", 9 I/O2 (io) "Data Input/Output", 10 I/O3 (io) "Data Input/Output", 11 VDD (power) "Power", 12 GND (power) "Ground", 13 I/O4 (io) "Data Input/Output", 14 I/O5 (io) "Data Input/Output", 15 I/O6 (io) "Data Input/Output", 16 I/O7 (io) "Data Input/Output", 17 ~{WE} (in) "Write Enable Input", 18 A10 (in) "Address Input", 19 A9 (in) "Address Input", 20 A8 (in) "Address Input", 21 A7 (in) "Address Input", 22 NC "No Connection", 23 NC "No Connection", 24 A6 (in) "Address Input", 25 A5 (in) "Address Input", 26 A4 (in) "Address Input", 27 A3 (in) "Address Input", 28 NC "No Connection", 29 I/O8 (io) "Data Input/Output", 30 I/O9 (io) "Data Input/Output", 31 I/O10 (io) "Data Input/Output", 32 I/O11 (io) "Data Input/Output", 33 VDD (power) "Power", 34 GND (power) "Ground", 35 I/O12 (io) "Data Input/Output", 36 I/O13 (io) "Data Input/Output", 37 I/O14 (io) "Data Input/Output", 38 I/O15 (io) "Data Input/Output", 39 ~{LB} (in) "Lower-byte Control (I/O0-I/O7)", 40 ~{UB} (in) "Upper-byte Control (I/O8-I/O15)", 41 ~{OE} (in) "Output Enable Input", 42 A2 (in) "Address Input", 43 A1 (in) "Address Input", 44 A0 (in) "Address Input"

## IS61WV6416DBLL-10TI-TR
designator U?
1 M High Speed Asynchronous CMOS SRAM, 64 K x 16, -40 to 85 degC, 44-Pin SOP (TSOP-2-44); Manufacturer: Integrated Silicon Solution Inc (ISSI); PartNumber: IS61WV6416DBLL-10TI-TR; Density: 1M; Organization: 64K x 16; Packing: Tape & Reel; Speed (ns): 10
footprint ISSI-TSOP-2-44_N (SOP, 44-Leads, Body 18.5x10.3mm, Pitch 0.8mm, IPC Medium Density)
pins: 1 A15 (in) "Address Input", 2 A14 (in) "Address Input", 3 A13 (in) "Address Input", 4 A12 (in) "Address Input", 5 A11 (in) "Address Input", 6 ~{CE} (in) "Chip Enable Input", 7 I/O0 (io) "Data Input/Output", 8 I/O1 (io) "Data Input/Output", 9 I/O2 (io) "Data Input/Output", 10 I/O3 (io) "Data Input/Output", 11 VDD (power) "Power", 12 GND (power) "Ground", 13 I/O4 (io) "Data Input/Output", 14 I/O5 (io) "Data Input/Output", 15 I/O6 (io) "Data Input/Output", 16 I/O7 (io) "Data Input/Output", 17 ~{WE} (in) "Write Enable Input", 18 A10 (in) "Address Input", 19 A9 (in) "Address Input", 20 A8 (in) "Address Input", 21 A7 (in) "Address Input", 22 NC "No Connection", 23 NC "No Connection", 24 A6 (in) "Address Input", 25 A5 (in) "Address Input", 26 A4 (in) "Address Input", 27 A3 (in) "Address Input", 28 NC "No Connection", 29 I/O8 (io) "Data Input/Output", 30 I/O9 (io) "Data Input/Output", 31 I/O10 (io) "Data Input/Output", 32 I/O11 (io) "Data Input/Output", 33 VDD (power) "Power", 34 GND (power) "Ground", 35 I/O12 (io) "Data Input/Output", 36 I/O13 (io) "Data Input/Output", 37 I/O14 (io) "Data Input/Output", 38 I/O15 (io) "Data Input/Output", 39 ~{LB} (in) "Lower-byte Control (I/O0-I/O7)", 40 ~{UB} (in) "Upper-byte Control (I/O8-I/O15)", 41 ~{OE} (in) "Output Enable Input", 42 A2 (in) "Address Input", 43 A1 (in) "Address Input", 44 A0 (in) "Address Input"

## IS61WV6416DBLL-10TLI
designator U?
1 M High Speed Asynchronous CMOS SRAM, 64 K x 16, -40 to 85 degC, 44-Pin SOP (TSOP-2-44), Pb-Free; Manufacturer: Integrated Silicon Solution Inc (ISSI); PartNumber: IS61WV6416DBLL-10TLI; Density: 1M; Organization: 64K x 16; Packing: Tray / Tube; Speed (ns): 10
footprint ISSI-TSOP-2-44_N (SOP, 44-Leads, Body 18.5x10.3mm, Pitch 0.8mm, IPC Medium Density)
pins: 1 A15 (in) "Address Input", 2 A14 (in) "Address Input", 3 A13 (in) "Address Input", 4 A12 (in) "Address Input", 5 A11 (in) "Address Input", 6 ~{CE} (in) "Chip Enable Input", 7 I/O0 (io) "Data Input/Output", 8 I/O1 (io) "Data Input/Output", 9 I/O2 (io) "Data Input/Output", 10 I/O3 (io) "Data Input/Output", 11 VDD (power) "Power", 12 GND (power) "Ground", 13 I/O4 (io) "Data Input/Output", 14 I/O5 (io) "Data Input/Output", 15 I/O6 (io) "Data Input/Output", 16 I/O7 (io) "Data Input/Output", 17 ~{WE} (in) "Write Enable Input", 18 A10 (in) "Address Input", 19 A9 (in) "Address Input", 20 A8 (in) "Address Input", 21 A7 (in) "Address Input", 22 NC "No Connection", 23 NC "No Connection", 24 A6 (in) "Address Input", 25 A5 (in) "Address Input", 26 A4 (in) "Address Input", 27 A3 (in) "Address Input", 28 NC "No Connection", 29 I/O8 (io) "Data Input/Output", 30 I/O9 (io) "Data Input/Output", 31 I/O10 (io) "Data Input/Output", 32 I/O11 (io) "Data Input/Output", 33 VDD (power) "Power", 34 GND (power) "Ground", 35 I/O12 (io) "Data Input/Output", 36 I/O13 (io) "Data Input/Output", 37 I/O14 (io) "Data Input/Output", 38 I/O15 (io) "Data Input/Output", 39 ~{LB} (in) "Lower-byte Control (I/O0-I/O7)", 40 ~{UB} (in) "Upper-byte Control (I/O8-I/O15)", 41 ~{OE} (in) "Output Enable Input", 42 A2 (in) "Address Input", 43 A1 (in) "Address Input", 44 A0 (in) "Address Input"

## IS61WV6416DBLL-10TLI-TR
designator U?
1 M High Speed Asynchronous CMOS SRAM, 64 K x 16, -40 to 85 degC, 44-Pin SOP (TSOP-2-44), Pb-Free; Manufacturer: Integrated Silicon Solution Inc (ISSI); PartNumber: IS61WV6416DBLL-10TLI-TR; Density: 1M; Organization: 64K x 16; Packing: Tape & Reel; Speed (ns): 10
footprint ISSI-TSOP-2-44_N (SOP, 44-Leads, Body 18.5x10.3mm, Pitch 0.8mm, IPC Medium Density)
pins: 1 A15 (in) "Address Input", 2 A14 (in) "Address Input", 3 A13 (in) "Address Input", 4 A12 (in) "Address Input", 5 A11 (in) "Address Input", 6 ~{CE} (in) "Chip Enable Input", 7 I/O0 (io) "Data Input/Output", 8 I/O1 (io) "Data Input/Output", 9 I/O2 (io) "Data Input/Output", 10 I/O3 (io) "Data Input/Output", 11 VDD (power) "Power", 12 GND (power) "Ground", 13 I/O4 (io) "Data Input/Output", 14 I/O5 (io) "Data Input/Output", 15 I/O6 (io) "Data Input/Output", 16 I/O7 (io) "Data Input/Output", 17 ~{WE} (in) "Write Enable Input", 18 A10 (in) "Address Input", 19 A9 (in) "Address Input", 20 A8 (in) "Address Input", 21 A7 (in) "Address Input", 22 NC "No Connection", 23 NC "No Connection", 24 A6 (in) "Address Input", 25 A5 (in) "Address Input", 26 A4 (in) "Address Input", 27 A3 (in) "Address Input", 28 NC "No Connection", 29 I/O8 (io) "Data Input/Output", 30 I/O9 (io) "Data Input/Output", 31 I/O10 (io) "Data Input/Output", 32 I/O11 (io) "Data Input/Output", 33 VDD (power) "Power", 34 GND (power) "Ground", 35 I/O12 (io) "Data Input/Output", 36 I/O13 (io) "Data Input/Output", 37 I/O14 (io) "Data Input/Output", 38 I/O15 (io) "Data Input/Output", 39 ~{LB} (in) "Lower-byte Control (I/O0-I/O7)", 40 ~{UB} (in) "Upper-byte Control (I/O8-I/O15)", 41 ~{OE} (in) "Output Enable Input", 42 A2 (in) "Address Input", 43 A1 (in) "Address Input", 44 A0 (in) "Address Input"

## IS61WV6416EEBLL-8BI
designator U?
1 M High Speed Asynchronous CMOS SRAM with ECC, 64 K x 16, -40 to 85 degC, 48-Pin BGA (TF-BGA-48); Manufacturer: Integrated Silicon Solution Inc (ISSI); PartNumber: IS61WV6416EEBLL-8BI; Density: 1M; Organization: 64K x 16; Packing: Tray / Tube; Speed (ns): 8
footprint ISSI-TF-BGA-48-6000X8000DE (BGA, 48-Balls, Body 8x6mm, Pitch 0.75mm)
part A pins: A1 ~{LB} (in) "Lower-byte Control (I/O0-I/O7)", A2 ~{OE} (in) "Output Enable Input", A3 A0 (in) "Address Input", A4 A1 (in) "Address Input", A5 A2 (in) "Address Input", B1 I/O8 (io) "Data Input/Output", B2 ~{UB} (in) "Upper-byte Control (I/O8-I/O15)", B3 A3 (in) "Address Input", B4 A4 (in) "Address Input", B5 ~{CE} (in) "Chip Enable Input", B6 I/O0 (io) "Data Input/Output", C1 I/O9 (io) "Data Input/Output", C2 I/O10 (io) "Data Input/Output", C3 A5 (in) "Address Input", C4 A6 (in) "Address Input", C5 I/O1 (io) "Data Input/Output", C6 I/O2 (io) "Data Input/Output", D1 GND (power) "Ground", D2 I/O11 (io) "Data Input/Output", D4 A7 (in) "Address Input", D5 I/O3 (io) "Data Input/Output", D6 VDD (power) "Power", E1 VDD (power) "Power", E2 I/O12 (io) "Data Input/Output", E5 I/O4 (io) "Data Input/Output", E6 GND (power) "Ground", F1 I/O14 (io) "Data Input/Output", F2 I/O13 (io) "Data Input/Output", F3 A14 (in) "Address Input", F4 A15 (in) "Address Input", F5 I/O5 (io) "Data Input/Output", F6 I/O6 (io) "Data Input/Output", G1 I/O15 (io) "Data Input/Output", G3 A12 (in) "Address Input", G4 A13 (in) "Address Input", G5 ~{WE} (in) "Write Enable Input", G6 I/O7 (io) "Data Input/Output", H2 A8 (in) "Address Input", H3 A9 (in) "Address Input", H4 A10 (in) "Address Input", H5 A11 (in) "Address Input"
part B pins: A6 NC "No Connection", D3 NC "No Connection", E3 NC "No Connection", E4 NC "No Connection", G2 NC "No Connection", H1 NC "No Connection", H6 NC "No Connection"

## IS61WV6416EEBLL-8BI-TR
designator U?
1 M High Speed Asynchronous CMOS SRAM with ECC, 64 K x 16, -40 to 85 degC, 48-Pin BGA (TF-BGA-48); Manufacturer: Integrated Silicon Solution Inc (ISSI); PartNumber: IS61WV6416EEBLL-8BI-TR; Density: 1M; Organization: 64K x 16; Packing: Tape & Reel; Speed (ns): 8
footprint ISSI-TF-BGA-48-6000X8000DE (BGA, 48-Balls, Body 8x6mm, Pitch 0.75mm)
part A pins: A1 ~{LB} (in) "Lower-byte Control (I/O0-I/O7)", A2 ~{OE} (in) "Output Enable Input", A3 A0 (in) "Address Input", A4 A1 (in) "Address Input", A5 A2 (in) "Address Input", B1 I/O8 (io) "Data Input/Output", B2 ~{UB} (in) "Upper-byte Control (I/O8-I/O15)", B3 A3 (in) "Address Input", B4 A4 (in) "Address Input", B5 ~{CE} (in) "Chip Enable Input", B6 I/O0 (io) "Data Input/Output", C1 I/O9 (io) "Data Input/Output", C2 I/O10 (io) "Data Input/Output", C3 A5 (in) "Address Input", C4 A6 (in) "Address Input", C5 I/O1 (io) "Data Input/Output", C6 I/O2 (io) "Data Input/Output", D1 GND (power) "Ground", D2 I/O11 (io) "Data Input/Output", D4 A7 (in) "Address Input", D5 I/O3 (io) "Data Input/Output", D6 VDD (power) "Power", E1 VDD (power) "Power", E2 I/O12 (io) "Data Input/Output", E5 I/O4 (io) "Data Input/Output", E6 GND (power) "Ground", F1 I/O14 (io) "Data Input/Output", F2 I/O13 (io) "Data Input/Output", F3 A14 (in) "Address Input", F4 A15 (in) "Address Input", F5 I/O5 (io) "Data Input/Output", F6 I/O6 (io) "Data Input/Output", G1 I/O15 (io) "Data Input/Output", G3 A12 (in) "Address Input", G4 A13 (in) "Address Input", G5 ~{WE} (in) "Write Enable Input", G6 I/O7 (io) "Data Input/Output", H2 A8 (in) "Address Input", H3 A9 (in) "Address Input", H4 A10 (in) "Address Input", H5 A11 (in) "Address Input"
part B pins: A6 NC "No Connection", D3 NC "No Connection", E3 NC "No Connection", E4 NC "No Connection", G2 NC "No Connection", H1 NC "No Connection", H6 NC "No Connection"

## IS61WV6416EEBLL-8BLI
designator U?
1 M High Speed Asynchronous CMOS SRAM with ECC, 64 K x 16, -40 to 85 degC, 48-Pin BGA (TF-BGA-48), Pb-Free; Manufacturer: Integrated Silicon Solution Inc (ISSI); PartNumber: IS61WV6416EEBLL-8BLI; Density: 1M; Organization: 64K x 16; Packing: Tray / Tube; Speed (ns): 8
footprint ISSI-TF-BGA-48-6000X8000DE (BGA, 48-Balls, Body 8x6mm, Pitch 0.75mm)
part A pins: A1 ~{LB} (in) "Lower-byte Control (I/O0-I/O7)", A2 ~{OE} (in) "Output Enable Input", A3 A0 (in) "Address Input", A4 A1 (in) "Address Input", A5 A2 (in) "Address Input", B1 I/O8 (io) "Data Input/Output", B2 ~{UB} (in) "Upper-byte Control (I/O8-I/O15)", B3 A3 (in) "Address Input", B4 A4 (in) "Address Input", B5 ~{CE} (in) "Chip Enable Input", B6 I/O0 (io) "Data Input/Output", C1 I/O9 (io) "Data Input/Output", C2 I/O10 (io) "Data Input/Output", C3 A5 (in) "Address Input", C4 A6 (in) "Address Input", C5 I/O1 (io) "Data Input/Output", C6 I/O2 (io) "Data Input/Output", D1 GND (power) "Ground", D2 I/O11 (io) "Data Input/Output", D4 A7 (in) "Address Input", D5 I/O3 (io) "Data Input/Output", D6 VDD (power) "Power", E1 VDD (power) "Power", E2 I/O12 (io) "Data Input/Output", E5 I/O4 (io) "Data Input/Output", E6 GND (power) "Ground", F1 I/O14 (io) "Data Input/Output", F2 I/O13 (io) "Data Input/Output", F3 A14 (in) "Address Input", F4 A15 (in) "Address Input", F5 I/O5 (io) "Data Input/Output", F6 I/O6 (io) "Data Input/Output", G1 I/O15 (io) "Data Input/Output", G3 A12 (in) "Address Input", G4 A13 (in) "Address Input", G5 ~{WE} (in) "Write Enable Input", G6 I/O7 (io) "Data Input/Output", H2 A8 (in) "Address Input", H3 A9 (in) "Address Input", H4 A10 (in) "Address Input", H5 A11 (in) "Address Input"
part B pins: A6 NC "No Connection", D3 NC "No Connection", E3 NC "No Connection", E4 NC "No Connection", G2 NC "No Connection", H1 NC "No Connection", H6 NC "No Connection"

## IS61WV6416EEBLL-8BLI-TR
designator U?
1 M High Speed Asynchronous CMOS SRAM with ECC, 64 K x 16, -40 to 85 degC, 48-Pin BGA (TF-BGA-48), Pb-Free; Manufacturer: Integrated Silicon Solution Inc (ISSI); PartNumber: IS61WV6416EEBLL-8BLI-TR; Density: 1M; Organization: 64K x 16; Packing: Tape & Reel; Speed (ns): 8
footprint ISSI-TF-BGA-48-6000X8000DE (BGA, 48-Balls, Body 8x6mm, Pitch 0.75mm)
part A pins: A1 ~{LB} (in) "Lower-byte Control (I/O0-I/O7)", A2 ~{OE} (in) "Output Enable Input", A3 A0 (in) "Address Input", A4 A1 (in) "Address Input", A5 A2 (in) "Address Input", B1 I/O8 (io) "Data Input/Output", B2 ~{UB} (in) "Upper-byte Control (I/O8-I/O15)", B3 A3 (in) "Address Input", B4 A4 (in) "Address Input", B5 ~{CE} (in) "Chip Enable Input", B6 I/O0 (io) "Data Input/Output", C1 I/O9 (io) "Data Input/Output", C2 I/O10 (io) "Data Input/Output", C3 A5 (in) "Address Input", C4 A6 (in) "Address Input", C5 I/O1 (io) "Data Input/Output", C6 I/O2 (io) "Data Input/Output", D1 GND (power) "Ground", D2 I/O11 (io) "Data Input/Output", D4 A7 (in) "Address Input", D5 I/O3 (io) "Data Input/Output", D6 VDD (power) "Power", E1 VDD (power) "Power", E2 I/O12 (io) "Data Input/Output", E5 I/O4 (io) "Data Input/Output", E6 GND (power) "Ground", F1 I/O14 (io) "Data Input/Output", F2 I/O13 (io) "Data Input/Output", F3 A14 (in) "Address Input", F4 A15 (in) "Address Input", F5 I/O5 (io) "Data Input/Output", F6 I/O6 (io) "Data Input/Output", G1 I/O15 (io) "Data Input/Output", G3 A12 (in) "Address Input", G4 A13 (in) "Address Input", G5 ~{WE} (in) "Write Enable Input", G6 I/O7 (io) "Data Input/Output", H2 A8 (in) "Address Input", H3 A9 (in) "Address Input", H4 A10 (in) "Address Input", H5 A11 (in) "Address Input"
part B pins: A6 NC "No Connection", D3 NC "No Connection", E3 NC "No Connection", E4 NC "No Connection", G2 NC "No Connection", H1 NC "No Connection", H6 NC "No Connection"

## IS61WV6416EEBLL-8TI
designator U?
1 M High Speed Asynchronous CMOS SRAM with ECC, 64 K x 16, -40 to 85 degC, 44-Pin SOP (TSOP-2-44); Manufacturer: Integrated Silicon Solution Inc (ISSI); PartNumber: IS61WV6416EEBLL-8TI; Density: 1M; Organization: 64K x 16; Packing: Tray / Tube; Speed (ns): 8
footprint ISSI-TSOP-2-44_N (SOP, 44-Leads, Body 18.5x10.3mm, Pitch 0.8mm, IPC Medium Density)
pins: 1 A15 (in) "Address Inputs", 2 A14 (in) "Address Inputs", 3 A13 (in) "Address Inputs", 4 A12 (in) "Address Inputs", 5 A11 (in) "Address Inputs", 6 ~{CE} (in) "Chip Enable Input", 7 I/O0 (io) "Data Inputs/Outputs", 8 I/O1 (io) "Data Inputs/Outputs", 9 I/O2 (io) "Data Inputs/Outputs", 10 I/O3 (io) "Data Inputs/Outputs", 11 VDD (power) "Power", 12 GND (power) "Ground", 13 I/O4 (io) "Data Inputs/Outputs", 14 I/O5 (io) "Data Inputs/Outputs", 15 I/O6 (io) "Data Inputs/Outputs", 16 I/O7 (io) "Data Inputs/Outputs", 17 ~{WE} (in) "Write Enable Input", 18 A10 (in) "Address Inputs", 19 A9 (in) "Address Inputs", 20 A8 (in) "Address Inputs", 21 A7 (in) "Address Inputs", 22 NC "No Connection", 23 NC "No Connection", 24 A6 (in) "Address Inputs", 25 A5 (in) "Address Inputs", 26 A4 (in) "Address Inputs", 27 A3 (in) "Address Inputs", 28 NC "No Connection", 29 I/O8 (io) "Data Inputs/Outputs", 30 I/O9 (io) "Data Inputs/Outputs", 31 I/O10 (io) "Data Inputs/Outputs", 32 I/O11 (io) "Data Inputs/Outputs", 33 VDD (power) "Power", 34 GND (power) "Ground", 35 I/O12 (io) "Data Inputs/Outputs", 36 I/O13 (io) "Data Inputs/Outputs", 37 I/O14 (io) "Data Inputs/Outputs", 38 I/O15 (io) "Data Inputs/Outputs", 39 ~{LB} (in) "Lower-byte Control (I/O0-I/O7)", 40 ~{UB} (in) "Upper-byte Control (I/O8-I/O15)", 41 ~{OE} (in) "Output Enable Input", 42 A2 (in) "Address Inputs", 43 A1 (in) "Address Inputs", 44 A0 (in) "Address Inputs"

## IS61WV6416EEBLL-8TI-TR
designator U?
1 M High Speed Asynchronous CMOS SRAM with ECC, 64 K x 16, -40 to 85 degC, 44-Pin SOP (TSOP-2-44); Manufacturer: Integrated Silicon Solution Inc (ISSI); PartNumber: IS61WV6416EEBLL-8TI-TR; Density: 1M; Organization: 64K x 16; Packing: Tape & Reel; Speed (ns): 8
footprint ISSI-TSOP-2-44_N (SOP, 44-Leads, Body 18.5x10.3mm, Pitch 0.8mm, IPC Medium Density)
pins: 1 A15 (in) "Address Inputs", 2 A14 (in) "Address Inputs", 3 A13 (in) "Address Inputs", 4 A12 (in) "Address Inputs", 5 A11 (in) "Address Inputs", 6 ~{CE} (in) "Chip Enable Input", 7 I/O0 (io) "Data Inputs/Outputs", 8 I/O1 (io) "Data Inputs/Outputs", 9 I/O2 (io) "Data Inputs/Outputs", 10 I/O3 (io) "Data Inputs/Outputs", 11 VDD (power) "Power", 12 GND (power) "Ground", 13 I/O4 (io) "Data Inputs/Outputs", 14 I/O5 (io) "Data Inputs/Outputs", 15 I/O6 (io) "Data Inputs/Outputs", 16 I/O7 (io) "Data Inputs/Outputs", 17 ~{WE} (in) "Write Enable Input", 18 A10 (in) "Address Inputs", 19 A9 (in) "Address Inputs", 20 A8 (in) "Address Inputs", 21 A7 (in) "Address Inputs", 22 NC "No Connection", 23 NC "No Connection", 24 A6 (in) "Address Inputs", 25 A5 (in) "Address Inputs", 26 A4 (in) "Address Inputs", 27 A3 (in) "Address Inputs", 28 NC "No Connection", 29 I/O8 (io) "Data Inputs/Outputs", 30 I/O9 (io) "Data Inputs/Outputs", 31 I/O10 (io) "Data Inputs/Outputs", 32 I/O11 (io) "Data Inputs/Outputs", 33 VDD (power) "Power", 34 GND (power) "Ground", 35 I/O12 (io) "Data Inputs/Outputs", 36 I/O13 (io) "Data Inputs/Outputs", 37 I/O14 (io) "Data Inputs/Outputs", 38 I/O15 (io) "Data Inputs/Outputs", 39 ~{LB} (in) "Lower-byte Control (I/O0-I/O7)", 40 ~{UB} (in) "Upper-byte Control (I/O8-I/O15)", 41 ~{OE} (in) "Output Enable Input", 42 A2 (in) "Address Inputs", 43 A1 (in) "Address Inputs", 44 A0 (in) "Address Inputs"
